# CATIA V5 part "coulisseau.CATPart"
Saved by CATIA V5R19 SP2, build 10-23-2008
Part number: coulisseau
Bounding box of the stored display mesh (mm): x -25 to 50, y -26.206 to 22.562, z -31.06 to 21.312
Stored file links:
  C:\Documents and Settings\jboiteux\Bureau\iao_jboiteux\Catia\non optiisé\iao final\coulisseau.CATPart
  C:\iao4\mecanisme a rouleaux.CATProduct
  C:\Documents and Settings\jboiteux\Bureau\iao_jboiteux\Catia\non optiisé\iao final\bati.CATPart
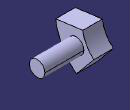
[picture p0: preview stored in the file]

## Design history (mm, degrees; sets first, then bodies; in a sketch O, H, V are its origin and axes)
Parameters
  taille = 10 mm {= External.taille}
External parameters (linked from other documents)
  External.taille = 10 mm
Body1 (main body)
  Sketch1 on yz-plane, origin (0, 0, 0), H (0, 1, 0), V (0, 0, 1)
    circle A1 centre (0, 0) radius 10
    radius A1 = 10 {= taille  *1}
  Pad1: profile Sketch1, direction (1, 0, 0), length 50 {= taille *5}
  Sketch2 on yz-plane, origin (0, 0, 0), H (0, 1, 0), V (0, 0, 1)
    arc A1 centre (48.1329, 26.6124) radius 40 from (8.4856, 21.3123) to (22.5616, -4.1464) ccw
    arc A2 centre (48.1329, 26.6124) radius 75 from (-26.2058, 16.6747) to (0.1867, -31.0605) ccw
    line L1 (22.5616, -4.1464) -> (0.1867, -31.0605)
    line L2 (8.4856, 21.3123) -> (-26.2058, 16.6747)
    point P5 (-26.2058, 16.6747)
    point P6 (-26.2058, 16.6747)
    radius A1 = 40 {= taille *4}
    radius A2 = 75 {= taille *7.5}
    distance A2 O = 20 {= taille  *2}
    distance L2 O = 20 {= taille  *2}
    distance L1 O = 20 {= taille  *2}
    length L2 = 35 {= taille  *3.5}
    length L1 = 35 {= taille *3.5}
    coincidence: P5 A2, P6 P5
  Pad2: profile Sketch2, direction (-1, 0, 0), length 25 {= taille  *2.5}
